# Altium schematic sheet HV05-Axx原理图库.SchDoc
size 127 x 99 mm
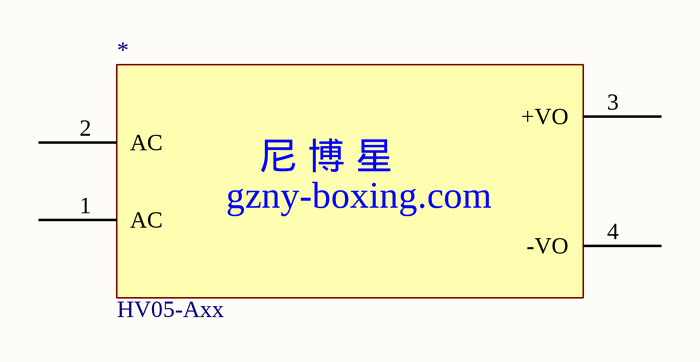
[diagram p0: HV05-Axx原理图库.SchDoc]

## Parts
*  HV05-Axx

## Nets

Not connected (* = marked no-connect by the designer): * 1(AC) 2(AC) 3(+VO) 4(-VO)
